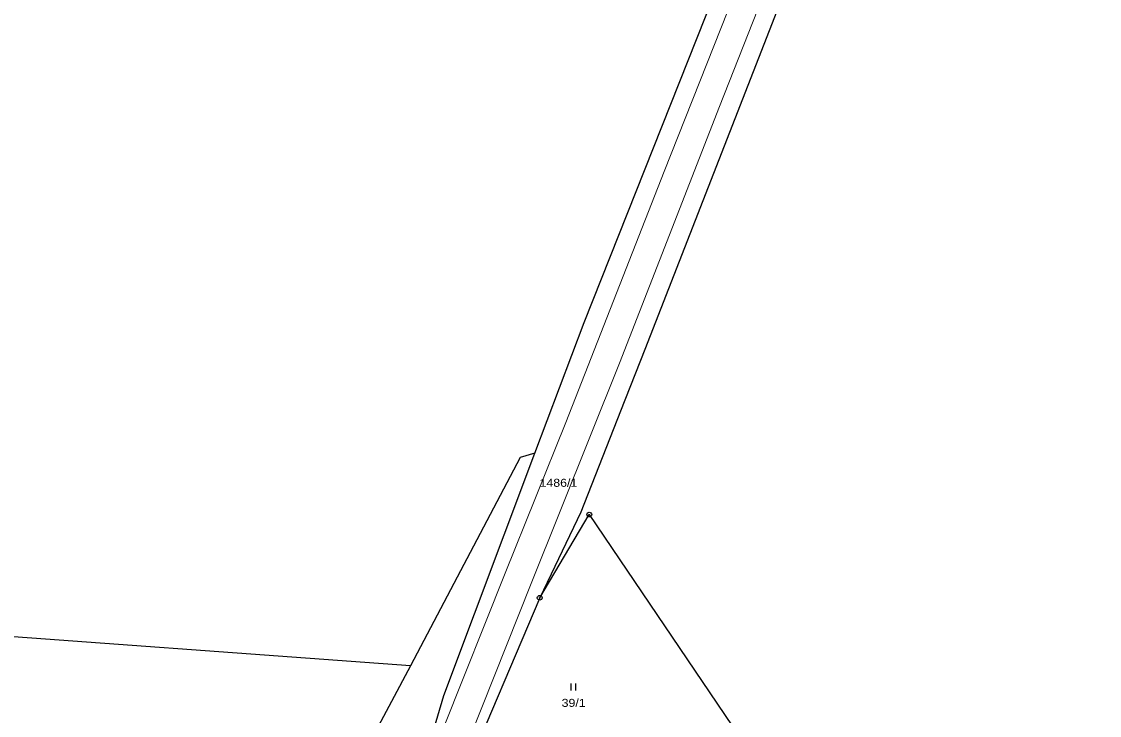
# Model space of a CAD drawing. Extents: x -872229 to -869198, y -1075981 to -1074329.
# Drawn here: x -871207 to -870978.1, y -1075083.8 to -1074936.4 of the extents above; entities that cross this region are included whole.
import ezdxf
from ezdxf.enums import TextEntityAlignment as Align

# ---------------------------------------------------------------- set-up
doc = ezdxf.new("R2010")
doc.units = 0
doc.header["$LTSCALE"] = 0.68
for name, color, linetype, lineweight in [('1', 7, 'Continuous', 25), ('3', 7, 'Continuous', 25), ('4', 7, 'Continuous', 13), ('8', 7, 'Continuous', 25)]:
    doc.layers.add(name, color=color, linetype=linetype, lineweight=lineweight)
doc.layers.add('2', color=7, linetype='Continuous')

msp = doc.modelspace()

# ---------------------------------------------------------------- linework, layer by layer
at = {"layer": '1'}
for points in [[(-870981.09, -1074678.49), (-870978.14, -1074698.51), (-870980.02, -1074733.6), (-870985.23, -1074766.42), (-870992.05, -1074792.43), (-871004.56, -1074826.1), (-871074.68, -1075006.03), (-871079.84, -1075019.17), (-871088.25, -1075040.59), (-871096.99, -1075058.79)], [(-871098, -1075028.09), (-871087.54, -1075000.31), (-871037.76, -1074874.85)], [(-871125.74, -1075108.09), (-871117.37, -1075079.56), (-871098, -1075028.09)], [(-871098, -1075028.09), (-871101.13, -1075029.01), (-871124.45, -1075073.24)], [(-871096.99, -1075058.79), (-871086.45, -1075041.13), (-871054.49, -1075088.37)], [(-871124.45, -1075073.24), (-871227.17, -1075065.71), (-871309.09, -1075059.71)], [(-871096.99, -1075058.79), (-871113.45, -1075097.58), (-871115.74, -1075103.81)], [(-871124.45, -1075073.24), (-871133.02, -1075089.5), (-871140.45, -1075111.97), (-871156.44, -1075128.18), (-871164.16, -1075134.61)]]:
    msp.add_lwpolyline(points, dxfattribs=at)
at = {"layer": '3'}
for p, q in [((-871090.311, -1075078.48), (-871090.311, -1075076.98)), ((-871089.31, -1075078.48), (-871089.31, -1075076.98))]:
    msp.add_line(p, q, dxfattribs=at)
at = {"layer": '4'}
for p, q in [((-871091.42, -1075021.56), (-871070.54, -1074968.25)), ((-871080.04, -1075008.93), (-871098.77, -1075055.79))]:
    msp.add_line(p, q, dxfattribs=at)
for points in [[(-871070.54, -1074968.25), (-871044.98, -1074903.65), (-871018.55, -1074837.46)], [(-871046.65, -1074923.52), (-871058.82, -1074954.4), (-871080.04, -1075008.93)], [(-871117.44, -1075086.44), (-871104.3, -1075053.55), (-871091.42, -1075021.56)], [(-871098.77, -1075055.79), (-871111.92, -1075088.68), (-871116.26, -1075103.1)]]:
    msp.add_lwpolyline(points, dxfattribs=at)
at = {"layer": '8'}
for centre, radius in [((-871086.45, -1075041.1299), 0.5), ((-871086.45, -1075041.1299), 0.0303), ((-871096.99, -1075058.7899), 0.5), ((-871096.99, -1075058.7899), 0.0303)]:
    msp.add_circle(centre, radius, dxfattribs=at)

# ---------------------------------------------------------------- texts
at = {"layer": '2', "width": 1.15}
msp.add_text('1486/1', height=1.7, dxfattribs=at).set_placement((-871093.009, -1075035.22), align=Align.CENTER)
msp.add_text('39/1', height=1.7, dxfattribs=at).set_placement((-871092.32, -1075081.97))

doc.saveas('drawing.dxf')
